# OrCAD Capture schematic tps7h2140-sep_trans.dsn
size B
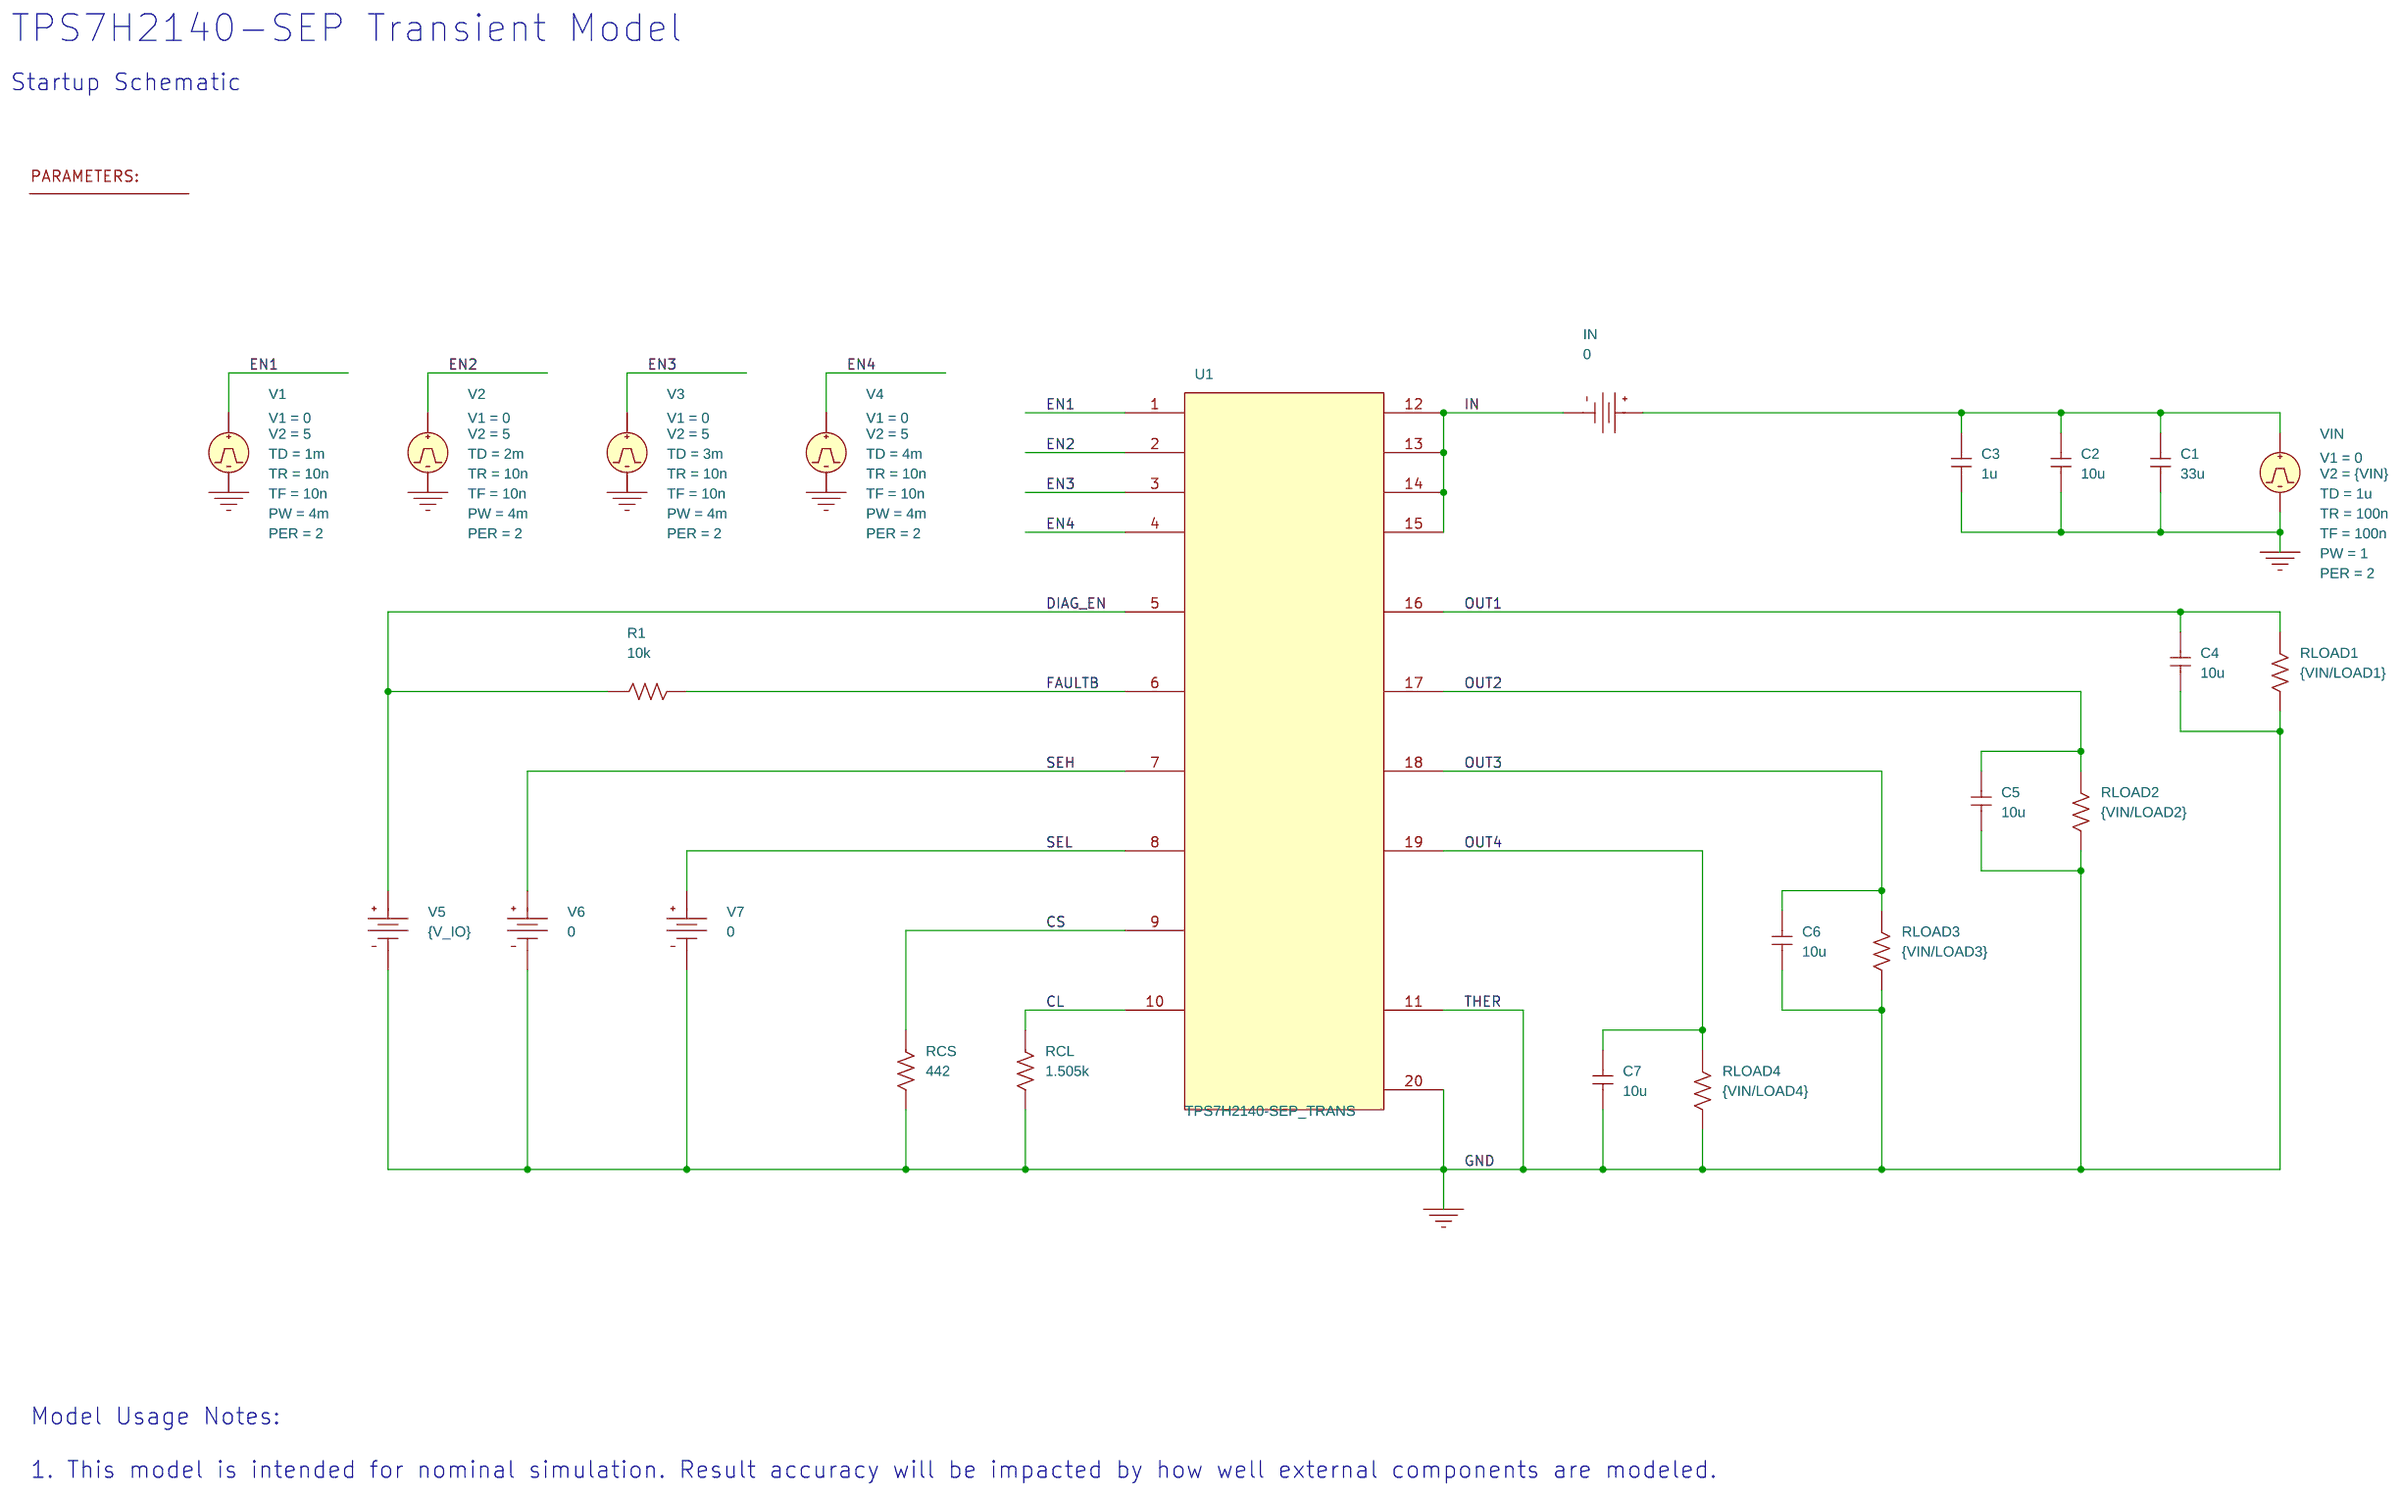
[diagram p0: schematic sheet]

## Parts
4  PARAM
C1  33u  [cap196]
C2  10u  [cap196]
C3  1u  [cap196]
C4  10u  [cap196]
C5  10u  [cap196]
C6  10u  [cap196]
C7  10u  [cap196]
IN  VDC
R1  10k  [AX/RC05]
RCL  1.505k  [AX/RC05]
RCS  442  [AX/RC05]
RLOAD1  {VIN/LOAD1}  [AX/RC05]
RLOAD2  {VIN/LOAD2}  [AX/RC05]
RLOAD3  {VIN/LOAD3}  [AX/RC05]
RLOAD4  {VIN/LOAD4}  [AX/RC05]
U1  TPS7H2140-SEP_TRANS
V1  VPULSE
V2  VPULSE
V3  VPULSE
V4  VPULSE
V5  VDC
V6  VDC
V7  VDC
VIN  VPULSE

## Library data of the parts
4 = PARAM: LOAD1: 0.5; LOAD2: 0.5; LOAD3: 0.5; LOAD4: 0.5; VIN: 12; V_IO: 5
C1-C7 = C
IN V6 V7 = VDC: DC: 0
R1 RCL RCS RLOAD1-RLOAD4 = R
U1 = TPS7H2140-SEP_TRANS_1
V1 = VPULSE: PER: 2; PW: 4m; TD: 1m; TF: 10n; TR: 10n; V1: 0; V2: 5
V2 = VPULSE: PER: 2; PW: 4m; TD: 2m; TF: 10n; TR: 10n; V1: 0; V2: 5
V3 = VPULSE: PER: 2; PW: 4m; TD: 3m; TF: 10n; TR: 10n; V1: 0; V2: 5
V4 = VPULSE: PER: 2; PW: 4m; TD: 4m; TF: 10n; TR: 10n; V1: 0; V2: 5
V5 = VDC: DC: {V_IO}
VIN = VPULSE: PER: 2; PW: 1; TD: 1u; TF: 100n; TR: 100n; V1: 0; V2: {VIN}

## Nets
0: C1.2 C2.2 C3.2 C4.2 C5.2 C6.2 C7.2 RCL.2 RCS.2 RLOAD1.2 RLOAD2.2 RLOAD3.2 RLOAD4.2 U1.11(THER) U1.20(GND) V1.2(-) V2.2(-) V3.2(-) V4.2(-) V5.1(-) V6.1(-) V7.1(-) VIN.2(-)
CL: RCL.1 U1.10(CL)
CS: RCS.1 U1.9(CS)
DIAG_EN: R1.1 U1.5(DIAG_EN) V5.0(+)
EN1: U1.1(EN1) V1.1(+)
EN2: U1.2(EN2) V2.1(+)
EN3: U1.3(EN3) V3.1(+)
EN4: U1.4(EN4) V4.1(+)
FAULTB: R1.2 U1.6(FAULTB)
IN: IN.1(-) U1.12(IN_1) U1.13(IN_2) U1.14(IN_3) U1.15(IN_4)
OUT1: C4.1 RLOAD1.1 U1.16(OUT1)
OUT2: C5.1 RLOAD2.1 U1.17(OUT2)
OUT3: C6.1 RLOAD3.1 U1.18(OUT3)
OUT4: C7.1 RLOAD4.1 U1.19(OUT4)
SEH: U1.7(SEH) V6.0(+)
SEL: U1.8(SEL) V7.0(+)
N04936: C1.1 C2.1 C3.1 IN.0(+) VIN.1(+)

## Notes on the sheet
- TPS7H2140-SEP Transient Model
- Startup Schematic
- Model Usage Notes:
  1. This model is intended for nominal simulation. Result accuracy will be impacted by how well external components are modeled.
